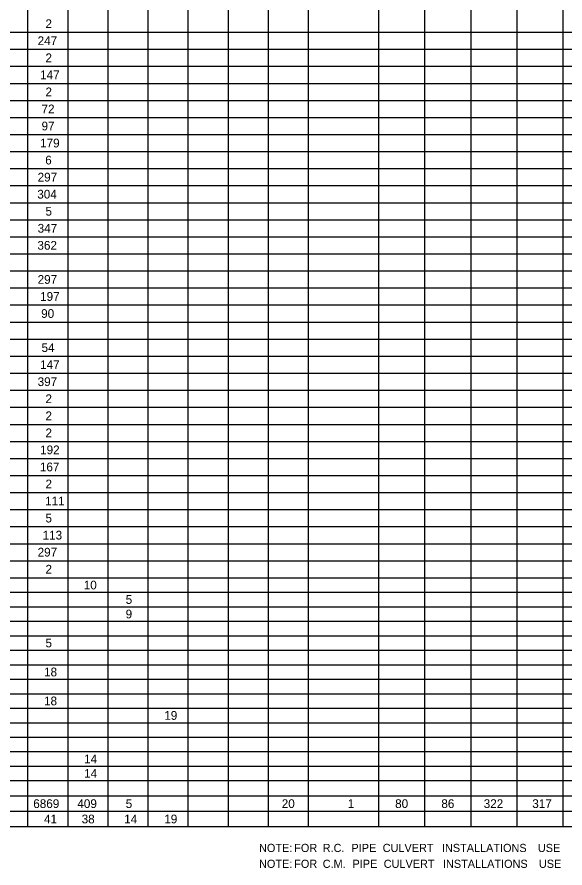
# Model space of a CAD drawing. Extents: x 1226564 to 1228153, y 151309 to 152340.
# Drawn here: x 1226835.5 to 1227102.4, y 151334.3 to 151749.1 of the extents above; entities that cross this region are included whole.
import ezdxf

# ---------------------------------------------------------------- set-up
doc = ezdxf.new("R2010")
doc.units = 0
doc.layers.add('R_Dimension', color=7, linetype='Continuous')

msp = doc.modelspace()

# ---------------------------------------------------------------- linework, layer by layer
at = {"layer": 'R_Dimension'}
for p, q in [((1226840.79, 151354.44), (1226840.79, 152160.49)), ((1226860.31, 151354.44), (1226860.31, 152115.62)), ((1226879.84, 151354.44), (1226879.84, 152115.62)), ((1226899.37, 151354.44), (1226899.37, 152115.62)), ((1226918.9, 151354.44), (1226918.9, 152115.62)), ((1226938.43, 151354.44), (1226938.43, 152115.62)), ((1226957.95, 151354.44), (1226957.95, 152115.62)), ((1226977.48, 151354.44), (1226977.48, 152115.62)), ((1227011.72, 151354.44), (1227011.72, 152115.62)), ((1227034.16, 151354.44), (1227034.16, 152115.62)), ((1227056.6, 151354.44), (1227056.6, 152115.62)), ((1227079.03, 151354.44), (1227079.03, 152115.62)), ((1227101.47, 151354.44), (1227101.47, 152115.62)), ((1226563.55, 151741.68), (1228152.75, 151741.68)), ((1226563.55, 151733.37), (1228152.75, 151733.37)), ((1226563.55, 151725.06), (1228152.75, 151725.06)), ((1226563.55, 151716.75), (1228152.75, 151716.75)), ((1226563.55, 151708.44), (1228152.75, 151708.44)), ((1226563.55, 151700.13), (1228152.75, 151700.13)), ((1226563.55, 151691.82), (1228152.75, 151691.82)), ((1226563.55, 151683.51), (1228152.75, 151683.51)), ((1226563.55, 151675.2), (1228152.75, 151675.2)), ((1226563.55, 151666.89), (1228152.75, 151666.89)), ((1226563.55, 151658.58), (1228152.75, 151658.58)), ((1226563.55, 151650.27), (1228152.75, 151650.27)), ((1226563.55, 151641.96), (1228152.75, 151641.96)), ((1226563.55, 151633.65), (1228152.75, 151633.65)), ((1226563.55, 151625.34), (1228152.75, 151625.34)), ((1226563.55, 151617.03), (1228152.75, 151617.03)), ((1226563.55, 151608.72), (1228152.75, 151608.72)), ((1226563.55, 151600.41), (1228152.75, 151600.41)), ((1226563.55, 151592.1), (1228152.75, 151592.1)), ((1226563.55, 151583.79), (1228152.75, 151583.79)), ((1226563.55, 151575.48), (1228152.75, 151575.48)), ((1226563.55, 151567.17), (1228152.75, 151567.17)), ((1226563.55, 151558.86), (1228152.75, 151558.86)), ((1226563.55, 151550.55), (1228152.75, 151550.55)), ((1226563.55, 151542.24), (1228152.75, 151542.24)), ((1226563.55, 151533.93), (1228152.75, 151533.93)), ((1226563.55, 151525.62), (1228152.75, 151525.62)), ((1226563.55, 151517.31), (1228152.75, 151517.31)), ((1226563.55, 151509), (1228152.75, 151509)), ((1226563.55, 151500.69), (1228152.75, 151500.69)), ((1226563.55, 151492.38), (1228152.75, 151492.38)), ((1226563.55, 151484.07), (1228152.75, 151484.07)), ((1226563.55, 151475.76), (1228152.75, 151475.76)), ((1226563.55, 151468.7), (1228152.75, 151468.7)), ((1226563.55, 151461.64), (1228152.75, 151461.64)), ((1226563.55, 151454.57), (1228152.75, 151454.57)), ((1226563.55, 151447.51), (1228152.75, 151447.51)), ((1226563.55, 151440.45), (1228152.75, 151440.45)), ((1226563.55, 151433.38), (1228152.75, 151433.38)), ((1226563.55, 151426.32), (1228152.75, 151426.32)), ((1226563.55, 151419.26), (1228152.75, 151419.26)), ((1226563.55, 151412.19), (1228152.75, 151412.19)), ((1226563.55, 151405.13), (1228152.75, 151405.13)), ((1226563.55, 151398.07), (1228152.75, 151398.07)), ((1226563.55, 151391), (1228152.75, 151391)), ((1226563.55, 151383.94), (1228152.75, 151383.94)), ((1226563.55, 151376.88), (1228152.75, 151376.88)), ((1226563.55, 151369.4), (1228152.75, 151369.4)), ((1226563.55, 151361.92), (1228152.75, 151361.92)), ((1226563.55, 151354.44), (1228152.75, 151354.44))]:
    msp.add_line(p, q, dxfattribs=at)

# ---------------------------------------------------------------- texts
for s, height, p in [('2', 4.26, (1226849.34, 151743.7)), ('247', 4.261, (1226845.52, 151735.39)), ('2', 4.26, (1226849.34, 151727.08)), ('147', 4.261, (1226846.72, 151718.77)), ('2', 4.26, (1226849.34, 151710.46)), ('72', 4.261, (1226847.43, 151702.15)), ('97', 4.261, (1226847.43, 151693.84)), ('179', 4.261, (1226846.71, 151685.53)), ('6', 4.26, (1226849.22, 151677.22)), ('297', 4.261, (1226845.52, 151668.91)), ('304', 4.261, (1226845.35, 151660.6)), ('5', 4.26, (1226849.34, 151652.29)), ('347', 4.261, (1226845.52, 151643.98)), ('362', 4.261, (1226845.42, 151635.67)), ('297', 4.261, (1226845.52, 151619.05)), ('197', 4.261, (1226846.72, 151610.74)), ('90', 4.261, (1226847.24, 151602.43)), ('54', 4.261, (1226847.43, 151585.81)), ('147', 4.261, (1226846.72, 151577.51)), ('397', 4.261, (1226845.52, 151569.2)), ('2', 4.26, (1226849.34, 151560.89)), ('2', 4.26, (1226849.34, 151552.58)), ('2', 4.26, (1226849.34, 151544.27)), ('192', 4.261, (1226846.72, 151535.96)), ('167', 4.261, (1226846.62, 151527.65)), ('2', 4.26, (1226849.34, 151519.34)), ('111', 4.261, (1226849.14, 151511.03)), ('5', 4.26, (1226849.34, 151502.72)), ('113', 4.261, (1226847.93, 151494.41)), ('297', 4.261, (1226845.52, 151486.1)), ('2', 4.26, (1226849.34, 151477.79)), ('10', 4.261, (1226867.98, 151470.1)), ('5', 4.26, (1226888.4, 151463.04)), ('9', 4.26, (1226888.38, 151455.97)), ('5', 4.26, (1226849.34, 151441.85)), ('18', 4.261, (1226848.64, 151427.72)), ('18', 4.261, (1226848.64, 151413.59)), ('19', 4.261, (1226907.2, 151406.53)), ('14', 4.261, (1226868.17, 151385.34)), ('14', 4.261, (1226868.17, 151378.28)), ('6869', 4.261, (1226843.39, 151363.53)), ('409', 4.261, (1226864.86, 151363.53)), ('5', 4.26, (1226888.4, 151363.53)), ('20', 4.261, (1226964.41, 151363.53)), ('1', 4.26, (1226996.56, 151363.53)), ('80', 4.261, (1227019.64, 151363.53)), ('86', 4.261, (1227042.14, 151363.53)), ('322', 4.261, (1227062.78, 151363.53)), ('317', 4.261, (1227086.43, 151363.53)), ('41', 4.261, (1226848.64, 151356.05)), ('38', 4.261, (1226866.96, 151356.05)), ('14', 4.261, (1226887.69, 151356.05)), ('19', 4.261, (1226907.2, 151356.05)), ('NOTE:', 3.965, (1226953.36, 151342.09)), (' FOR', 3.965, (1226969.03, 151342.09)), (' R.C.', 3.965, (1226982.89, 151342.09)), (' PIPE', 3.965, (1226996.91, 151342.09)), (' CULVERT', 3.965, (1227012.11, 151342.09)), (' INSTALLATIONS', 3.9647, (1227040.96, 151342.09)), (' USE', 3.965, (1227087.69, 151342.09)), ('NOTE:', 3.965, (1226953.36, 151334.36)), (' FOR', 3.965, (1226969.03, 151334.36)), (' C.M.', 3.965, (1226982.89, 151334.36)), (' PIPE', 3.965, (1226997.41, 151334.36)), (' CULVERT', 3.965, (1227012.61, 151334.36)), (' INSTALLATIONS', 3.9647, (1227041.46, 151334.36)), (' USE', 3.965, (1227088.19, 151334.36))]:
    msp.add_text(s, height=height, dxfattribs=at).set_placement(p)

doc.saveas('drawing.dxf')
